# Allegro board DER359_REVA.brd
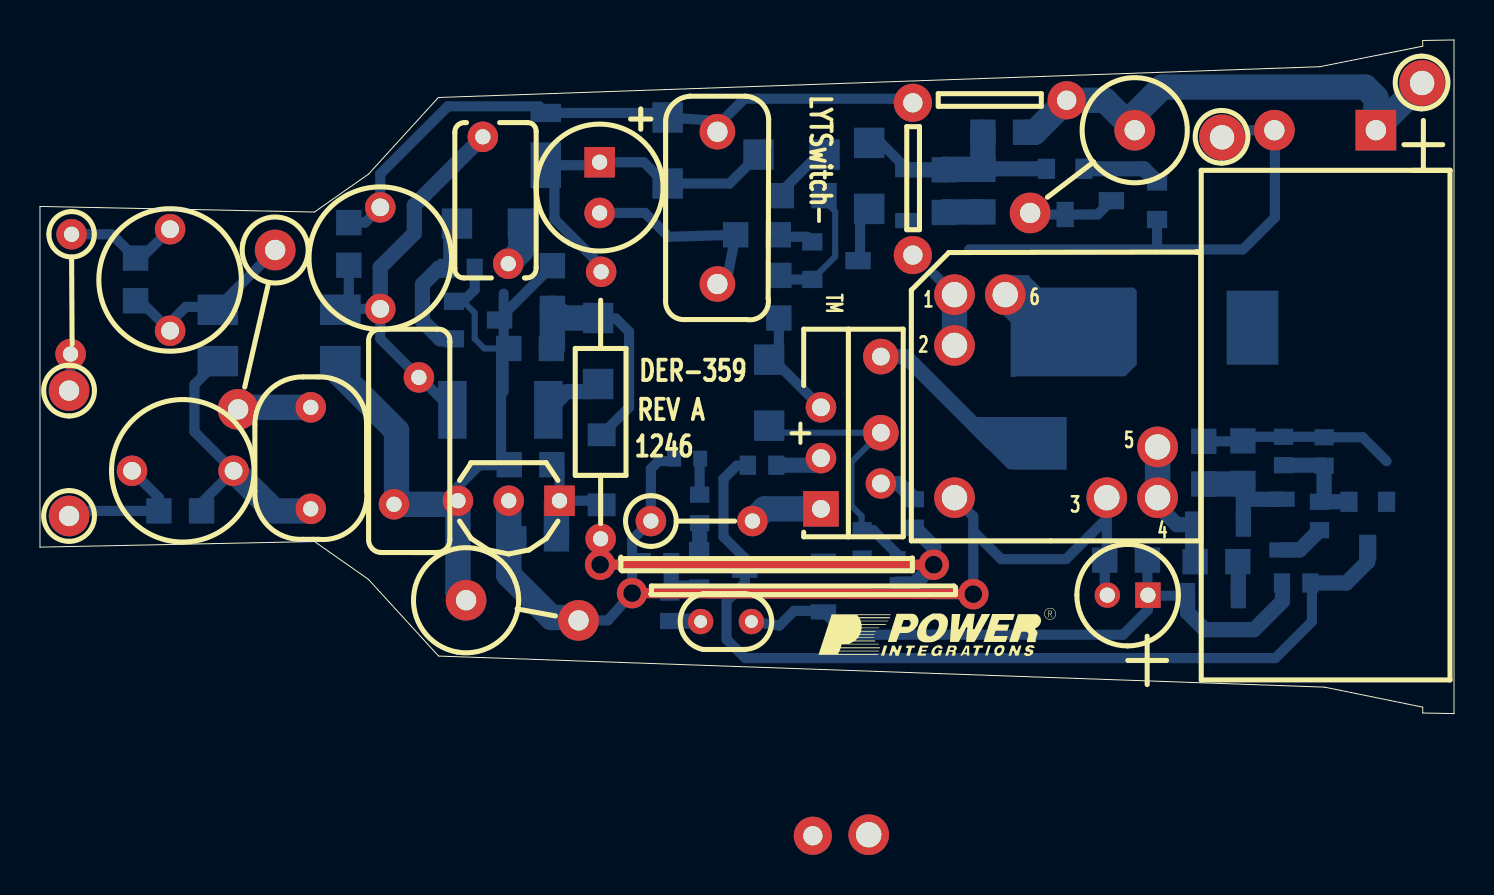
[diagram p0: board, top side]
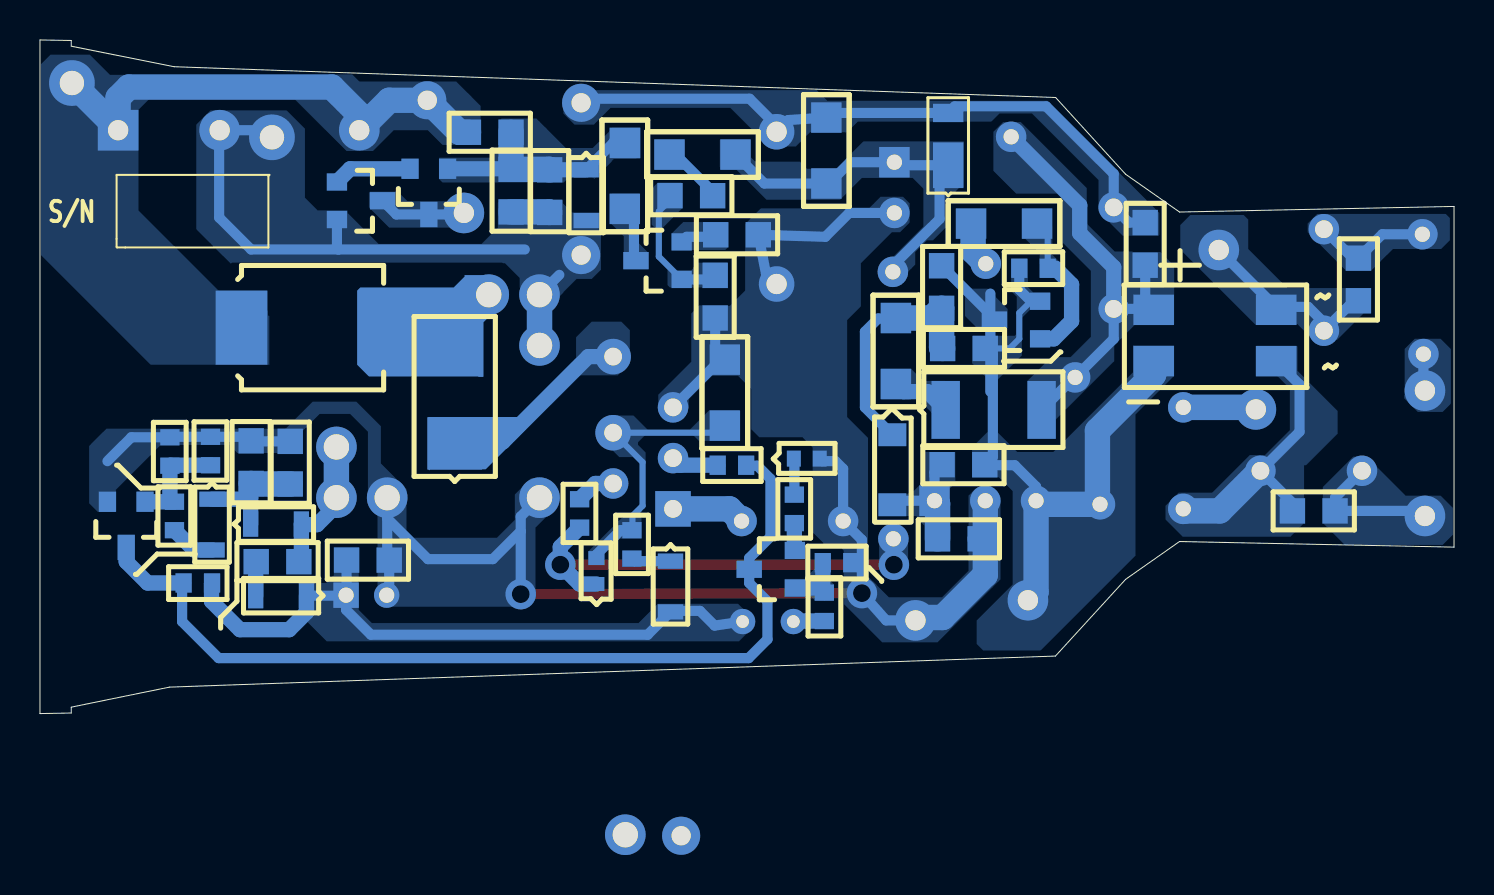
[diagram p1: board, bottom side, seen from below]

Outline 70.74 x 33.71 mm; copper layers: TOP, BOTTOM. Coordinates in mm from the lower left corner of the outline.
Outline path: 0,25.38 0,8.33 13.73,8.61 16.43,6.72 19.94,2.88 64.26,1.32 69.18,0.32 69.18,0.03 70.74,0 70.74,33.71 69.18,33.68 69.18,33.4 64.03,32.37 19.93,30.83 16.43,26.99 13.73,25.1 0,25.38

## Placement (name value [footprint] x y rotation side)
BR1  B10S-G  [PISMSOIC4]  8.9 17.64 90 bottom
C1  10 nF  [PINPCAPRAD440X160250030]  18.98 16.82 270 top
C3  100 nF  [PI_NP_CAPRAD320X235LS200D030]  13.55 15.32 270 top
C4  180 nF  [PINPCAPRAD440X200300040]  33.89 29.12 270 top
C5  2.2 uF  [PIPOLCAPCYLD250LS100030]  28 27.59 270 top
C6  330 uF  [PIPOLCAPCLYD500LS200040]  66.83 29.19 180 bottom
C8  100 uF  [PISMC1206]  36.48 14.41 90 bottom
C9  22  uF  [PIPOLCAPCLYD200LS80030]  55.43 5.93 180 top
C10  100 nF  [PISMC0603]  64.24 13.83 270 bottom
C11  1 uF  [PISMC0805]  45.24 25.08 90 bottom
C13  1 uF  [PISMC0805]  58.22 11.49 90 bottom
C14  100 nF  [PISMC0805]  25.59 18.27 180 bottom
C15  100 pF  [PINPCAPRAD250X160250030]  22.16 28.86 270 top
C16  1.2 nF  [PISMC0805]  25.61 12.45 180 bottom
D2  DFLR1600-7  [PISMDDFLR120012]  25.31 27.41 270 bottom
D3  ES3G-E3/57T  [PISMDO214AB12]  60.66 19.31 180 bottom
D5  BAV21WS-7-F  [PISMSOD323]  43.42 27.21 270 bottom
D6  BAV21WS-7-F  [PISMSOD323]  57.41 5.9 0 bottom
D7  ES2D  [PISMDO214AA12]  49.99 13.52 90 bottom
D8  BAV21WS-7-F  [PISMSOD323]  39.2 7.63 270 bottom
D9  DL4002  [PISMDMLL4112]  25.43 15.2 180 bottom
D10  BAV21WS-7-F  [PISMSOD323]  60.21 9.48 180 bottom
D11  MA2S1110GL  [PISMDSOD52312]  42.91 6.48 90 bottom
F1  2 A  [PIVAXIALD100LS100030]  1.58 23.99 270 top
J1  PCB Terminal 22 AWG  [PI_HOLE_22AWG]  69.15 31.55 0 top
J2  PCB Terminal 22 AWG  [PI_HOLE_22AWG]  59.14 28.84 0 top
JP1  J  [PI_JUMPER300#2]  43.67 30.56 270 top
JP2  J  [PI_JUMPER300]  43.75 30.69 0 top
L  CON1  [PITPKEYSTONE100X100]  1.46 16.16 0 top
L1  1 mH  [PICHOKE030DIALS200035]  6.51 24.24 270 top
L2  1 mH  [PICHOKE030DIALS200035]  4.6 12.15 0 top
L3  1 mH  [PICHOKE030DIALS200035]  17.03 25.33 270 top
N  CON1  [PITPKEYSTONE100X100]  1.46 9.89 0 top
NOREF  -  []  38.95 2.88 0 top
NOREF#2  -  []  70.74 0 90 top
NOREF#3  -  []  -150.78 54.55 0 top
NOREF#4  -  []  -228.59 -144.47 0 top
NOREF#5  -  []  19.93 30.83 0 top
NOREF#6  -  []  0 25.38 0 top
NOREF#7  -  []  0 8.33 90 top
Q4  FMMT459TA  [PISMSOT23132]  38.64 23.6 90 bottom
Q5  MMBT3904  [PISMSOT23132]  67.37 10.6 0 bottom
Q6  MMT493TA  [PISMSOT23132]  55.89 24.72 270 bottom
Q8  MMBT3904  [PISMSOT23132]  32.98 8.16 90 bottom
Q9  DSC2C01S0L  [PISMSOT23132]  52.23 27.26 0 bottom
Q10  STQ3N45K3-AP  [PIT092100]  25.99 10.65 180 top
Q12  FMMT459TA  [PISMSOT23132]  20.71 20.63 90 bottom
R1  10 k  [PISMR0805]  4.78 22.79 270 bottom
R2  10 k  [PISMR0805]  5.95 10.14 0 bottom
R3  10 k  [PISMR0805]  15.45 22.44 90 bottom
R4  1.0 k  [PI12WVRESD180LS150D040]  11.77 23.2 258.6 top
R8  510 k  [PISMR1206]  31.4 29.83 270 bottom
R9  2.00 M  [PI14WRESD100LS500D030]  28.05 21.45 270 top
R10  24.9 k  [PI14WRESD100LS400D030]  30.56 9.63 0 top
R11  6.2 k  [PISMR0603]  41.13 7.75 90 bottom
R12  140 k  [PISMR0603]  63.56 6.54 180 bottom
R14  1 k  [PISMR0603]  64.02 10.6 270 bottom
R15  20 k  [PISMR0603]  62.21 13.85 270 bottom
R16  130  [PI2WRESD200LS725D040#2]  21.32 5.67 350.3 top
R19  1.8 M  [PISMR0805]  47.18 29.09 0 bottom
R20  47 k  [PISMR1206]  41.49 28.56 270 bottom
R21  3.3 k  [PI2WRESD200LS725D040]  54.77 29.19 217.7 top
R23  51  [PISMR0805]  57.79 7.6 0 bottom
R25  20 k  [PISMR0805]  55.4 7.68 180 bottom
R26  1 M  [PISMR0805]  36.96 21.93 270 bottom
R28  470 k  [PISMR0805]  36.94 23.96 180 bottom
R33  3.48 k  [PISMR0603]  30.16 7.55 0 bottom
R34  20 k  [PISMR0603]  35.42 12.43 0 bottom
R35  10 k  [PISMR0805]  60.18 11.51 90 bottom
R36  51 k  [PISMR0603]  43.75 10.73 270 bottom
R37  2.00 M  [PISMR1206]  35.95 27.97 0 bottom
R38  470 k  [PISMR0805]  37.09 25.92 0 bottom
R39  100 k  [PISMR0805]  47.18 27.24 270 bottom
R40  4.7 k  [PISMR0603]  33 10.95 270 bottom
R43  750 k  [PISMR1206]  27.92 19.79 270 bottom
R44  240 k  [PISMR1206]  24.16 24.52 180 bottom
R45  100 k  [PISMR0603]  20.33 22.28 0 bottom
R46  4.7 k  [PISMR0805]  25.64 22.41 270 bottom
R47  180 k  [PISMR0805]  25.84 8.75 180 bottom
R48  4.75 k  [PISMR0603]  31.5 4.63 90 bottom
RT1  100 k  [PI_RAD_118X118_LS100D025]  35.59 4.6 180 top
T1  RM5  [PI_BOBBIN_RM5_6P_CLP]  45.75 20.96 180 top
U1  LYT4312E  [PIICESIP76TH]  39.07 10.24 90 top
VR1  MAZS1000  [PISMDSOD52312]  33.03 12.76 180 bottom
VR3  MMSZ5257BS-7-F  [PISMSOD323]  62.14 10.73 270 bottom
VR4  BZT52C15-7-F  [PI_SM_SOD-123_12]  28.1 13.95 270 bottom

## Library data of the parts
BR1 = DIODE BRIDGE_~~+-: room: 1
C1 C3 = CAP NP: room: 1
C4 C8 C10 C11 C14-C16 = CAP NP
C5 = CAP POL: alternate symbols: (pipolcapcyld250ls100030h)
C6 = CAP POL: alternate symbols: (pipolcapclyd500ls2000401000lh)
C9 = CAP POL
C13 = CAP NP_1: tolerance: 10
D2 D3 D5-D8 D10 D11 = DIODE
D9 = DIODE: room: 1
F1 = FUSE: room: 1
J1 J2 = TERM_1Pin
JP1 JP2 = JUMPER_1
L N = TESTPOINT: room: 1
L1-L3 = INDUCTOR: room: 1
Q4-Q6 Q8 Q9 Q12 = NPN_BEC
Q10 = FET_N_GDS
R1-R3 = R: room: 1
R4 = R: alternate symbols: (pi12wvresd180ls200d040,pi12wvresd180ls250d040,pi12wresd180ls675d040); room: 1
R8 R11 R12 R14 R15 R19 R20 R23 R25 R26 R28 R33 R34 R36-R40 R43-R48 = R
R9 R10 = R: alternate symbols: (pi14wvresd100ls200d030,pi14wresd100ls400d030,pi14wresd100ls500d030)
R16 = R: alternate symbols: (pi2wresd200ls900d040,pi2wvresd200ls300d040,pi2wvresd200ls400d040); tolerance: 5%
R21 = R: alternate symbols: (pi2wresd200ls900d040,pi2wvresd200ls300d040,pi2wvresd200ls400d040)
R35 = R: tolerance: 5%
RT1 = THERMISTOR
T1 = BRM6_6P_CLP
U1 = LNK40X_eSIP
VR1 VR3 VR4 = DIODE_ZENER

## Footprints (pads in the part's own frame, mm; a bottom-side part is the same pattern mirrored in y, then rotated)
PI2WRESD200LS725D040
  round 2.032 hole 1.016: 1(0,0) 2(6.672,0.075)
PI2WRESD200LS725D040#2
  round 2.032 hole 1.016: 1(0,0) 2(5.715,-0.051)
PI12WVRESD180LS150D040
  round 2.032 hole 1.016: 1(0,0) 2(8.185,-0.242)
PI14WRESD100LS400D030
  round 1.524 hole 0.762: 1(0,0) 2(5.08,0)
PI14WRESD100LS500D030
  round 1.524 hole 0.762: 1(-0.66,0.025) 2(12.7,0)
PI_BOBBIN_RM5_6P_CLP
  round 2.032 hole 1.27: 1(0,0) 2(0,2.54) 3(-7.62,10.16) 4(-10.16,10.16) 5(-10.16,7.62) 6(-2.54,0) CLP1(4.293,27.026) CLP2(0,10.16)
PI_HOLE_22AWG
  round 2.286 hole 1.219: 1(0,0)
PI_JUMPER300
  round 1.905 hole 0.965: 1(-5.08,-36.805) 2(7.62,0)
PI_JUMPER300#2
  round 1.905 hole 0.965: 1(0,0) 2(7.62,0)
PI_NP_CAPRAD320X235LS200D030
  round 1.524 hole 0.762: 1(0,0) 2(5.08,0)
PI_RAD_118X118_LS100D025
  round 1.27 hole 0.635: 1(0,0) 2(2.54,0)
PI_SM_SOD-123_12
  rect 1.143x1.397 smd: 1(0,0) 2(3.505,0)
PICHOKE030DIALS200035
  round 1.524 hole 0.889: 1(0,0) 2(5.08,0)
PIICESIP76TH
  rect 1.778x1.778 hole 0.889: 1(0,0)
  round 1.524 hole 0.889: 2(1.27,-2.997) 3(2.54,0) 5(5.08,0)
  round 1.778 hole 0.889: 4(3.81,-2.997) 7(7.62,-2.997)
PINPCAPRAD250X160250030
  round 1.524 hole 0.762: 1(0,0) 2(6.35,1.27)
PINPCAPRAD440X160250030
  round 1.524 hole 0.762: 1(0,-0.025) 2(6.35,-1.27)
PINPCAPRAD440X200300040
  round 1.778 hole 1.016: 1(0,0) 2(7.62,0)
PIPOLCAPCLYD200LS80030
  rect 1.27x1.27 hole 0.762: 1(0,0)
  round 1.27 hole 0.762: 2(2.032,0)
PIPOLCAPCLYD500LS200040
  rect 2.032x2.032 hole 1.016: 1(0,0)
  round 2.032 hole 1.016: 2(5.08,0)
PIPOLCAPCYLD250LS100030
  rect 1.524x1.524 hole 0.762: 1(0,0)
  round 1.524 hole 0.762: 2(2.54,0)
PISMC0603
  rect 0.813x0.965 smd: 1(0,0) 2(1.422,0)
PISMC0805
  rect 1.27x1.27 smd: 1(0,0) 2(2.134,0)
PISMC1206
  rect 1.524x1.524 smd: 1(0,0) 2(3.302,0)
PISMDDFLR120012
  rect 2.286x1.524 smd: 1(-0.025,0)
  rect 0.914x1.524 smd: 2(-2.642,0)
PISMDMLL4112
  rect 1.422x2.896 smd: 1(0,0) 2(4.801,0)
PISMDO214AA12
  rect 2.616x2.743 smd: 1(0,0) 2(4.699,0)
PISMDO214AB12
  rect 2.591x3.708 smd: 1(0,0) 2(7.112,0)
PISMDSOD52312
  rect 0.699x0.8 smd: 1(0,0) 2(1.295,0)
PISMR0603
  rect 0.813x0.965 smd: 1(0,0) 2(1.422,0)
PISMR0805
  rect 1.27x1.27 smd: 1(0,0) 2(2.134,0)
PISMR1206
  rect 1.524x1.524 smd: 1(0,0) 2(3.302,0)
PISMSOD323
  rect 0.762x1.27 smd: 1(0,0) 2(2.54,0)
PISMSOIC4
  rect 1.524x2.032 smd: 1(0,0) 2(2.57,0) 3(2.57,6.129) 4(0,6.129)
PISMSOT23132
  rect 0.864x1.016 smd: 1(-1.88,0) 2(0,0)
  rect 0.864x1.27 smd: 3(-0.94,2.286)
PIT092100
  rect 1.524x1.524 hole 0.762: 1(0,0)
  round 1.524 hole 0.762: 2(2.54,0) 3(5.08,0)
PITPKEYSTONE100X100
  round 2.032 hole 1.016: 1(0,0)
PIVAXIALD100LS100030
  round 1.524 hole 0.762: 1(0,0) 2(5.994,-0.051)

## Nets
GND: C4.2 C5.2 C8.2 C9.2 C10.1 C13.2 Q5.2(EMITTER) Q10.2(D) R10.1 R15.1 R16.2 R25.2 R26.2 R28.2 R33.1 R35.2 R47.2 T1.3 T1.CLP2 U1.5(S) VR1.2
BULK: C4.1 D2.2 JP1.1 JP2.1 L3.1 R3.2 R8.1
PK_DET: C5.1 D2.1 R8.2 R9.1 R37.1
N2191708: F1.1 L1.1 R1.1
N2229506: BR1.4 C1.2 C14.2 C16.2 Q10.3(S) Q12.2(EMITTER) R16.1 R45.2
N2232323: L2.1 N.1 R2.1
N2302506: F1.2 L.1
N2488145: BR1.1 C3.2 L2.2 R2.2
N2488295: BR1.2 L1.2 R1.2 R4.1
N2491459: C8.1 D11.2 R11.2 U1.4(BP)
N2492720: D7.1 U1.7(D)
N2492766: R10.2 U1.1(R)
N2493445: C6.2 C11.1 D5.2 J2.1 JP1.2 Q6.2(EMITTER) R39.2 T1.1 T1.2
N2532048: R34.2 U1.3(FB)
N2538393: BR1.3 C1.1 C15.1 D9.2 L3.2 R3.1
N2539922: C9.1 D6.1 D8.2 R12.2 R25.1 RT1.1
N2541951: D11.1 R9.2 R36.2
N3203198: R14.2 VR3.2
N3203318: C10.2 Q5.1(BASE) R14.1 R15.2
N3653162: C3.1 R4.2
N3672068: C6.1 D3.1 J1.1 JP2.2 R19.2 R21.1
N3707878: D3.2 D7.2 T1.6
N3708267: D6.2 R23.2
N3717582: Q4.1(BASE) R26.1 R38.2
N3718510: C11.2 D5.1 Q9.1(BASE) R19.1 R20.1 R39.1
N3718685: D8.1 R11.1
N3718886: Q5.3(COLLECTOR) Q8.3(COLLECTOR) R12.1 R34.1
N3734797: Q4.2(EMITTER) R28.1
N3737040: Q8.1(BASE) R33.2 R48.2
N3739420: C13.1 D10.1 R35.1 VR3.1
N3740281: R36.1 U1.2(V)
N3740360: D10.2 R23.1 T1.4 T1.5
N3742281: Q4.3(COLLECTOR) R20.2
N3742707: R37.2 R38.1
N3743778: Q6.1(BASE) Q9.2(EMITTER)
N3743785: Q6.3(COLLECTOR) Q9.3(COLLECTOR) R21.2
N3766853: C15.2 R44.1
N3766857: Q12.1(BASE) R44.2 R45.1
N3768407: Q12.3(COLLECTOR) R46.1
N3768414: C14.1 R43.1 R46.2 VR4.1
N3769856: D9.1 R43.2
N3777751: C16.1 Q10.1(G) R47.1 VR4.2
N3792762: R48.1 RT1.2
N37101521: R40.1 VR1.1
N37370032: Q8.2(EMITTER) R40.2

Pads without a net: T1 CLP1

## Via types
v1: diameter 1.524, hole 0.889, TOP to BOTTOM, 4 vias

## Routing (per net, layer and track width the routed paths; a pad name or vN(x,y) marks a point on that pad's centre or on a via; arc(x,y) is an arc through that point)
GND: length 86.7
  TOP w0.508: v1(46.69,5.98) v1(29.62,6.03)
  BOTTOM w0.508: 67.37,12.63 66.17,13.83 C10.1 64.22,13.85 R15.1 60.38,13.85 R35.2 60.15,13.62 C13.2 58.17,13.67 ; 53.37,11.54 T1.3 53.37,9.77 ; 53.37,9.77 51.33,7.73 48.09,7.73 46.69,9.13 ; 53.37,9.77 53.37,7.78 R25.2 53.27,6.05 C9.2 ; 46.69,9.13 v1(46.69,5.98) ; 46.69,9.13 46.69,9.86 T1.CLP2 ; C4.2 34.42,22.03 R28.2 31.45,23.86 30.26,25.05 C5.2 ; 23.2,16.11 23.2,21.01 ; R26.2 36.96,18.19 C8.2 36.48,17.91 U1.5 ; R16.2 28.41,4.66 v1(29.62,6.03) 29.62,8.69 R10.1 30.56,12.25 30.94,12.63 31.61,12.63 VR1.2
  BOTTOM w1.27: Q10.2 23.45,8.95 ; 23.45,8.95 R47.2 ; 23.45,8.95 23.45,6.94 25.59,4.81 26.8,4.81 R16.2
BULK: length 33
  BOTTOM w0.508: JP1.1 43.47,30.77 35.24,30.77 33.89,29.42 C4.1 33.31,29.7 R8.1 31.2,30.06 D2.2 24.98,30.39 20.4,30.39 17.03,27.01 L3.1 16.26,24.57 R3.2
PK_DET: length 19.1
  BOTTOM w0.508: R9.1 28.05,22.11 27.97,22.03 27.97,22.51 25.74,24.75 25.74,27.01 D2.1 27.85,27.44 C5.1 30.21,27.59 31.48,26.32 ; 31.48,26.32 R8.2 34.5,26.53 R37.1 ; 31.48,26.32 31.27,26.12
N2191708: length 6
  BOTTOM w0.508: L1.1 5.06,22.79 R1.1 3.59,23.99 F1.1
N2229506: length 33.2
  BOTTOM w0.305: 21.17,20.63 21.75,20.05 21.75,18.75 22.23,18.27 C14.2 23.38,18.35
  BOTTOM w0.508: Q12.2 21.17,20.63 21.75,21.22 R45.2 ; C14.2 23.07,17.89 23.07,12.86 C16.2 23.45,12.43 21.98,12.43 20.91,11.36 Q10.3
  BOTTOM w1.27: R16.1 20.91,6.08 Q10.3 20.73,10.47 C1.2 17.84,10.6 17.84,14.16 15.03,16.97 BR1.4
N2232323: length 7.2
  BOTTOM w0.508: L2.1 5.95,10.8 R2.1 1.71,10.14 N.1
N2302506: length 1.9
  BOTTOM w0.508: F1.2 1.53,16.24 L.1
N2488145: length 14.2
  BOTTOM w0.508: BR1.1 7.73,16.47 7.73,14.1 L2.2 8.08,10.55 R2.2
  BOTTOM w1.27: L2.2 9.71,12.15 11.72,10.14 13.44,10.14 C3.2
N2488295: length 9.7
  BOTTOM w0.508: R4.1 8.9,20.33 BR1.2 8.75,20.35 7.3,20.35 6.51,19.57 L1.2 5.01,20.66 R1.2
N2491459: length 13.9
  BOTTOM w0.305: R11.2 41.1,9.2 41.1,9.89 40.6,10.4 40.6,12.58 U1.4 36.84,14.05 C8.1
  BOTTOM w0.508: D11.2 42.93,7.86 42.93,7.93 41.69,9.18 R11.2
N2492720: length 9.7
  BOTTOM w0.762: U1.7 43.31,17.86 47.58,13.6 49.92,13.6 D7.1
N2492766: length 3.7
  BOTTOM w1.27: U1.1 36.25,10.24 R10.2
N2493445: length 30.5
  BOTTOM w0.508: 55.81,23.22 60.18,23.22 61.78,24.82 61.78,29.17 C6.2 59.49,29.19 J2.1 ; 55.81,23.22 46.49,23.22 ; 55.81,23.22 55.89,23.3 Q6.2 ; 44.76,21.95 T1.1
  BOTTOM w1.27: T1.1 T1.2 ; R39.2 45.27,25.1 C11.1
N2532048: length 2.4
  BOTTOM w0.762: U1.3 38.72,12.43 R34.2
N2538393: length 21.7
  BOTTOM w0.508: D9.2 19.01,16.82 C1.1 17.03,18.75 L3.2 15.07,20.25 ; 15.07,20.25 15.45,20.63 R3.1 ; 15.07,20.25 BR1.3
  BOTTOM w0.762: C15.1 18.73,25.43 18.73,24.04 17.03,22.33 L3.2
N2539922: length 33.1
  BOTTOM w0.508: C9.1 55.4,5.95 R25.1 ; C9.1 55.43,5.19 54.19,3.94 40.34,3.94 D8.2 39.15,5.14 37.73,5.14 36.99,4.4 RT1.1 ; C9.1 55.46,5.9 D6.1
  BOTTOM w0.762: R12.2 62.16,6.51 62.16,5.62 60.74,4.2 58.28,4.2 57.41,5.06 D6.1
N2541951: length 22.8
  TOP w0.508: v1(28.02,7.45) v1(44.71,7.45)
  BOTTOM w0.508: R9.2 28.05,7.48 v1(28.02,7.45)
  BOTTOM w0.762: D11.1 43.75,6.48 v1(44.71,7.45) ; v1(44.71,7.45) 44.71,7.09 ; v1(44.71,7.45) 44.71,8.34 R36.2
N3203198: length 2.3
  BOTTOM w0.762: VR3.2 63.02,8.19 R14.2
N3203318: length 5.4
  BOTTOM w0.762: R15.2 64.22,12.43 C10.2 64.24,10.83 R14.1 Q5.1
N3653162: length 3.7
  BOTTOM w1.27: C3.1 10.02,15.32 R4.2
N3672068: length 25.3
  BOTTOM w1.27: 66.83,29.24 66.83,30.82 66.3,31.35 56.14,31.35 54.77,29.98 R21.1 53.27,30.69 JP2.2 49.77,29.09 R19.2 ; 66.83,29.24 J1.1 ; 66.83,29.24 C6.1
N3707878: length 3.6
  BOTTOM w0.508: 49.82,18.19 49.82,19.79 48.65,20.96 T1.6
N3708267: length 1.7
  BOTTOM w0.762: R23.2 59.95,7.58 D6.2
N3717582: length 6.7
  BOTTOM w0.305: Q4.1 39.78,22.87 39.78,25.13 39.23,25.69 R38.2
  BOTTOM w0.508: Q4.1 37.17,21.72 R26.1
N3718510: length 11.3
  BOTTOM w0.508: D5.1 42.07,28.56 R20.1
  BOTTOM w0.762: D5.1 C11.2 ; R39.1 47.2,27.26 Q9.1
  BOTTOM w1.27: R19.1 R39.1 45.27,27.24 C11.2
N3718685: length 2
  BOTTOM w0.508: D8.1 41,7.63 R11.1
N3718886: length 46.8
  BOTTOM w0.508: R34.1 35.39,12.4 34.86,12.4 34.2,11.74 34.2,8.85 35.26,7.78 Q8.3 35.26,6.54 34.35,5.62 34.35,3.72 35.29,2.78 61.81,2.78 63.63,4.6 63.63,6.46 R12.1
  BOTTOM w0.762: R12.1 65.36,6.54 66.43,7.6 Q5.3
N3734797: length 1.8
  BOTTOM w0.508: Q4.2 38.39,23.86 37.04,23.86 R28.1
N3737040: length 3
  BOTTOM w0.762: R33.2 31.58,6.13 ; 31.58,6.13 31.73,6.28 Q8.1 ; 31.58,6.13 R48.2
N3739420: length 6
  BOTTOM w0.762: R35.1 60.21,11.49 60.21,10.8 ; 60.21,10.8 60.28,10.73 VR3.1 ; 60.21,10.8 D10.1
  BOTTOM w1.27: C13.1 60.15,11.49 R35.1
N3740281: length 2
  BOTTOM w0.762: U1.2 42.96,11.51 R36.1
N3740360: length 7
  BOTTOM w0.762: T1.4 55.91,10.42 56.88,9.46 57.64,9.46 D10.2 57.67,7.73 R23.1
  BOTTOM w1.27: T1.5 T1.4
N3742281: length 2.8
  BOTTOM w0.508: Q4.3 41.03,22.77 41.03,24.8 R20.2
N3742707: length 3.1
  BOTTOM w0.508: R38.1 37.09,26.12 38.95,27.97 R37.2
N3743778: length 3.9
  BOTTOM w0.762: Q6.1 55.23,27.26 Q9.2
N3743785: length 4.4
  BOTTOM w0.508: Q6.3 52.92,24.98 Q9.3 49.61,24.98 R21.2
N3766853: length 2.7
  BOTTOM w0.508: 23.22,22.21 C15.2
  BOTTOM w1.27: C15.2 24.06,23.15 24.06,24.42 R44.1
N3766857: length 7.9
  BOTTOM w0.305: R45.1 20.33,23.99 R44.2
  BOTTOM w0.508: 20.35,22.41 20.4,22.36 R45.1
  BOTTOM w0.762: Q12.1 20.02,18.75 19.13,19.64 19.13,21.47 19.95,22.28 R45.1
N3768407: length 3.8
  BOTTOM w0.508: Q12.3 22.99,19.77 R46.1
N3768414: length 12.1
  BOTTOM w0.508: VR4.1 29.47,15.32 29.47,19.11 28.81,19.77 27.95,19.77 R43.1
  BOTTOM w1.27: C14.1 25.64,18.32 R46.2 26.12,19.79 R43.1
N3769856: length 3.1
  BOTTOM w0.508: 25.51,15.32 25.56,15.32
  BOTTOM w0.762: R43.2 27.54,16.11 26.35,16.11 D9.1
N3777751: length 6.1
  BOTTOM w0.508: C16.1 25.99,12.07 Q10.1 27.9,10.65 VR4.2
  BOTTOM w1.27: R47.1 25.84,10.5 Q10.1
N3792762: length 1.6
  BOTTOM w0.762: R48.1 33.03,4.63 RT1.2
N37101521: length 1.8
  BOTTOM w0.508: VR1.1 33,12.73 R40.1
N37370032: length 1.4
  BOTTOM w0.762: Q8.2 33,8.19 R40.2

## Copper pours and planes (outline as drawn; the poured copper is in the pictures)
GND on BOTTOM: 46.18,11.77 46.98,10.97 46.98,9.7 47.89,8.8 52.13,8.8 52.41,9.08 52.41,11.23 53.69,12.52 53.69,14.38 54.92,15.61 57.11,15.61 57.11,15.6 58.45,14.26 67.42,14.26 68.28,13.39 68.28,10.52 67.85,10.09 67.01,10.09 66.94,10.17 66.94,11.16 66.96,11.18 64.7,13.44 61.27,13.44 60.87,13.04 57.59,13.04 57.59,14.16 56.75,14.99 55.23,14.99 54.34,14.1 54.34,10.5 53.86,10.02 53.86,5.95 53.25,5.34 46.36,5.34 45.96,5.75 45.96,9.3 45.07,10.19 45.07,11.34 45.5,11.77
GND on BOTTOM: 30.36,14.84 30.36,19.69 29.67,20.38 29.67,22.54 28.13,24.09 27.72,24.09 27.24,24.57 27.24,25.53 27.57,25.86 28.68,25.86 29.27,25.28 34.68,25.28 35.47,24.49 35.47,21.17 36.23,20.4 36.33,20.4 36.35,20.43 37.75,20.43 38.16,20.02 38.16,17.61 39.81,15.96 39.81,15.27 39.56,15.02 38.56,15.02 38.29,15.3 38.29,15.76 37.14,16.9 35.82,16.9 35.16,16.24 35.16,14.23 34.75,13.83 32.6,13.83 32.09,13.32 32.09,9.08 31.5,8.49 30.89,8.49 30.87,8.52 29.32,8.52 29.32,13.8
GND on BOTTOM: 30.89,8.52 30.54,8.16 30.54,5.93 29.98,5.37 29.47,5.37 28.89,5.95 28.89,6.43 29.34,6.89 29.34,8.67 29.62,8.95 30.79,8.95 30.89,8.85
GND on BOTTOM: 29.07,6.61 28.28,5.82 25.61,5.82 24.29,7.14 24.29,10.9 23.91,11.29 23.12,11.29 22.69,10.85 22.69,6.71 25.84,3.56 28.61,3.56 30.51,5.47 30.51,6.31 30.21,6.61
BULK on BOTTOM: 14.74,23.96 14.74,25.05 20.35,30.67 31.35,30.67 31.88,31.2 44.15,31.2 44.56,30.79 44.56,30.03 44,29.47 43.04,29.47 42.2,30.31 36.2,30.31 34.27,28.38 32.93,28.38 32.21,29.09 30.46,29.09 30.44,29.07 30.39,29.07 29.83,29.62 23.15,29.62 22.74,30.03 21.11,30.03 17.79,26.7 17.79,25.13 16.57,23.91 14.79,23.91
PK_DET on BOTTOM: 24.54,28.63 29.55,28.63 30.92,27.26 32.37,27.26 32.72,27.62 34.96,27.62 35.21,27.87 35.21,28.73 36.69,28.73 36.74,28.68 36.74,27.36 36.61,27.24 35.92,27.24 34.4,25.71 30.72,25.71 29.62,26.8 27.08,26.8 26.55,26.27 26.55,24.37 28.38,22.54 28.38,22.28 28.13,22.03 27.39,22.03 26.96,22.46 26.96,23.1 26.37,23.68 26.07,23.68 25.46,24.29 25.46,25.51 25.51,25.56 24.7,26.37 24.52,26.37 24.52,28.61
N2191708 on BOTTOM: 0.41,25 6.84,25 7.32,24.52 7.32,24.09 5.39,22.16 4.15,22.16 3.06,23.25 0.64,23.25 0.21,23.68 0.21,24.8
N2229506 on BOTTOM: 22.16,22.74 22.16,21.14 21.88,20.86 21.88,19.69 21.83,19.64 21.78,19.64 21.19,20.23 20.2,20.23 20.2,21.04 20.23,21.06 20.99,21.06 21.01,21.04 21.32,21.34 21.32,22.74 21.34,22.77 22.13,22.77
N2229506 on BOTTOM: 21.98,18.91 21.88,19.01 21.88,19.08 21.75,19.08 21.62,18.96 21.62,17.91 22.94,16.59 23.17,16.59 24.11,17.53 24.11,18.85 24.06,18.91
N2229506 on BOTTOM: 24.11,11.82 22.77,11.82 22.08,11.13 22.08,6.46 23.88,4.66 23.88,3.49 23.55,3.16 20.68,3.16 15.93,7.91 15.93,14.97 14,16.9 14,18.4 14.03,18.42 16.06,18.42 16.06,17.08 20.05,13.09 21.85,13.09 23.05,14.28 23.15,14.28 24.11,13.32
N2232323 on BOTTOM: 6.56,9.53 6.56,11.34 5.04,12.86 4.38,12.86 2.42,10.9 0.67,10.9 0.06,10.29 0.06,8.95 0.57,8.44 5.47,8.44
N2302506 on BOTTOM: 2.47,15.96 2.47,18.24 1.96,18.75 0.67,18.75 0.16,18.24 0.16,15.5 0.57,15.1 1.81,15.1 2.5,15.78 2.5,15.93
N2488145 on BOTTOM: 9.89,16.92 8.87,16.92 8.21,16.26 8.21,14.18 9.46,12.94 10.22,12.94 12.1,11.06 13.77,11.06 14.43,10.4 14.43,9.71 13.57,8.85 8.19,8.85 7.5,9.53 7.5,12.43 7.4,12.43 5.82,14 5.82,15.15 7.83,17.15 7.83,18.37 7.86,18.4 9.84,18.4 9.89,18.35
N2488295 on BOTTOM: 4.58,21.29 8.34,21.29 10.29,23.25 10.29,24.72 10.52,24.95 13.19,24.95 13.7,24.44 13.7,23.22 9.94,19.46 8.01,19.46 7.98,19.49 7.83,19.49 7.04,18.7 5.85,18.7 4.53,20.02 4.53,21.24
N2491459 on BOTTOM: 40.65,8.75 40.65,10.24 40.7,10.29 40.9,10.29 41.33,9.86 41.56,9.86 43.29,8.14 43.29,7.48 43.31,7.45 42.5,7.45 42.48,7.48 42.48,8.01 41.74,8.75
N2491459 on BOTTOM: 40.22,14.1 40.24,14.1 41.05,14.92 42.15,14.92 42.15,13.22 41.77,12.83 41,12.83 40.7,12.53 40.44,12.53 40.44,13.06 40.83,13.44 40.83,13.57 40.39,14 40.11,14
N2491459 on BOTTOM: 35.77,15.17 37.27,15.17 38.29,14.16 37.78,13.65 35.75,13.65 35.72,13.67 35.72,15.12
N2492720 on BOTTOM (solid shape): 46.59,14.84 51.32,14.84 51.32,12.22 51.26,12.17 51.21,12.22 48.45,12.22 46.46,14.21 46.46,14.97
N2492720 on BOTTOM: 43.92,17.71 43.92,18.83 43.14,19.62 41.66,19.62 41.23,19.18 41.23,17.53 41.84,16.92 44.13,16.92 44.13,17.51
N2493445 on BOTTOM: 47.58,22.54 47.48,22.54 46.74,21.8 46.74,21.32 45.85,20.43 45.19,20.43 44.56,21.06 44.56,21.09 43.9,21.75 43.14,21.75 42.68,22.21 42.68,25.08 44.13,25.08 44.58,25.53 44.58,25.66 44.64,25.71 47.68,25.71 47.84,25.56 47.84,24.32 48.65,23.5 53.8,23.5 55.35,25.05 55.35,25.18 56.85,25.18 57.49,25.81 57.49,29.27 58.4,30.18 62.21,30.18 62.92,29.47 62.92,24.24 61.2,22.51 61.14,22.56 47.61,22.56
N2538393 on BOTTOM: 16.06,23.1 14.69,23.1 14,22.41 14,19.49 14.05,19.44 15.98,19.44 17,18.42 17,17.64 19.95,14.69 19.95,13.77 19.97,13.75 21.34,13.75 21.34,16.64 20.15,17.84 19.18,17.84 18.17,18.85 18.17,22.16 19.57,23.55 19.57,25.76 19.82,26.02 21.9,26.02 23.05,27.16 23.05,29.12 22.56,29.6 21.67,29.6 18.37,26.3 18.37,24.52 16.97,23.12 16.09,23.12
N2539922 on BOTTOM: 56.04,8.34 56.04,6.92 56.42,6.54 57.79,6.54 57.79,5.01 56.4,3.61 35.77,3.61 35.19,4.2 35.19,4.86 35.82,5.49 39.83,5.49 40.8,4.53 54.13,4.53 54.8,5.19 54.8,8.29 54.85,8.34
N2541951 on BOTTOM: 28.76,8.87 28.76,7.2 28.68,7.12 27.97,7.12 27.31,7.78 27.31,8.72 27.69,9.1 28.53,9.1
N3672068 on BOTTOM: 59.34,19.95 59.34,20.15 59.93,20.73 61.37,20.73 65.82,25.18 65.82,30.21 64.83,31.2 64.83,31.58 65.21,31.96 67.24,31.96 68.26,32.98 70.21,32.98 70.7,32.49 70.7,22.94 65.21,17.46 59.27,17.46 59.27,19.87
N3672068 on BOTTOM: 49.92,31.63 54.77,31.63 55.13,31.99 56.45,31.99 57.39,31.05 58.3,31.05 55.4,28.15 54.08,28.15 53.04,29.19 51.34,29.19 50.6,28.46 48.7,28.46 48.7,30.41
N3707878 on BOTTOM (solid shape): 49.5,21.86 50.05,21.32 54.72,21.32 54.87,21.17 54.87,17.46 54.29,16.87 48.83,16.87 48.8,16.85 48.57,16.85 48.56,16.86 48.56,19.58 47.71,20.43 47.61,20.43 47.61,21.5 48.05,21.94 49.5,21.94
N3717582 on BOTTOM: 37.57,22.56 37.78,22.56 38.16,22.18 39.15,22.18 39.35,22.38 39.35,21.45 39.23,21.32 36.38,21.32 36.35,21.34 36.35,22.56 36.38,22.59 37.55,22.59
N3717582 on BOTTOM: 39.83,26.58 40.14,26.27 40.14,24.47 39.78,24.11 38.62,25.28 38.62,26.53 38.67,26.58
N3718510 on BOTTOM: 42.1,29.32 42.1,29.29 43.09,28.3 44.43,28.3 45.91,29.78 47.66,29.78 47.78,29.65 47.78,28.28 48.24,27.82 50.76,27.82 50.78,27.8 50.78,26.75 50.6,26.58 44.53,26.58 44.25,26.86 43.11,26.86 43.01,26.75 42.15,27.62 42.15,27.64 42.03,27.76 40.89,27.76 40.88,27.77 40.72,27.77 40.67,27.82 40.67,29.32
N3734797 on BOTTOM: 36.3,24.59 38.56,24.59 39.12,24.04 39.12,23.2 36.46,23.2 36.3,23.35
N3737040 on BOTTOM: 33.48,6.74 32.49,6.74 31.96,7.27 31.17,7.27 31.17,6.74 31.2,6.71 31.2,6.64 31.02,6.46 31.02,5.7 31.07,5.65 31.96,5.65 32.16,5.85 33.48,5.85
N3742281 on BOTTOM: 42.22,24.52 42.17,24.52 41.54,23.88 41.54,22.28 41.56,22.26 40.32,22.26 40.29,22.28 40.29,23.05 40.77,23.53 40.77,25.97 40.72,26.02 42.17,26.02 42.22,25.97
N3743785 on BOTTOM: 49.69,25.64 52.36,25.64 52.84,26.12 54.24,26.12 54.29,26.07 54.29,25.33 53.27,24.32 49.72,24.32 49.69,24.34
N3766857 on BOTTOM: 20.73,22.51 20.73,23.05 21.45,23.76 21.45,24.42 20.15,24.42 20.1,24.37 20.1,22.97 19.67,22.54 19.67,22.41 19.84,22.23 20.45,22.23
N3768407 on BOTTOM: 22.33,19.26 22.33,20.25 23.35,21.27 24.37,21.27 24.47,21.17 24.47,19.9 23.86,19.29 22.36,19.29
N3769856 on BOTTOM: 25.48,16.64 26.55,16.64 27.16,17.25 28.66,17.25 28.68,17.23 28.68,15.78 28.63,15.73 27.29,15.73 27.21,15.81 26.88,15.81 26.02,14.94 25.26,14.94 25.18,15.02 25.18,16.34
N3777751 on BOTTOM: 25.56,10.93 25.56,9.35 25.51,9.3 25.56,9.25 26.35,9.25 26.83,9.74 26.83,9.81 26.91,9.89 28.79,9.89 28.79,11.03 27.44,11.03 27.41,11.01 27.16,11.01 26.55,11.62 26.55,13.04 26.5,13.09 24.95,13.09 24.95,11.54

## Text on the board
Ref Des/Silkscreen Bottom: S/N
Ref Des/Silkscreen Top: TM | 1246 | REV A | DER-359 | LYTSwitch-
User.7: 13   MATERIAL FR4 COPPER 2oz THICKNESS 0.031" | PLEASE DELETTE THESE PINS
User.9: FIGURE | SIZE | 25.0 | 30.0 | 35.0 | 38.0 | 40.0 | 48.0 | 50.0 | DRILL CHART: TOP to BOTTOM | ALL UNITS ARE IN MILS | QTY | 2 | 19 | 12 | 4 | 8
